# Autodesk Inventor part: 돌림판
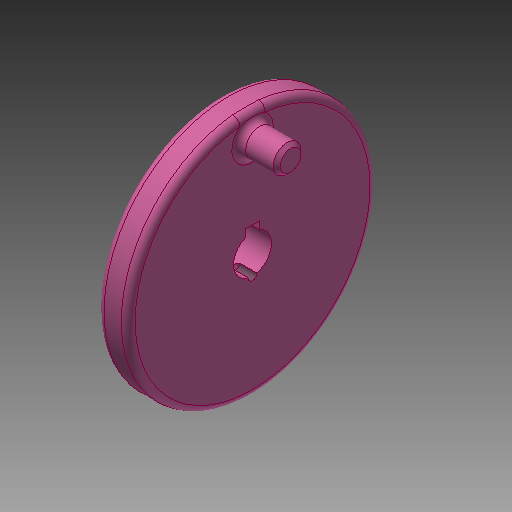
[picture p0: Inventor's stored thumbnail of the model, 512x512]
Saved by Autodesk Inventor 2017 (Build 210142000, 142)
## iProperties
Created: 2019-09
Part Number: 돌림판
Material: 알루미늄 6061
Document SubType Name: Modeling
Designer: mduedu
Density: 2.71 g/cm^3
Mass: 83.7231 g
Surface Area: 107.333 cm^2
Volume: 30.8941 cm^3
Appearance: 분홍색
Author: mduedu
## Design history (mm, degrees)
sketch "스케치1"
  geometry: L1 (0, 0)-(9, 0); L2 (9, 0)-(9, 36); L3 (9, 36)-(0, 36); L4 (0, 23)-(4, 23); L5 (4, 23)-(4, 10); L6 (4, 10)-(0, 10); L7 (0, 36)-(0, 23); L8 (0, 10)-(0, 0)
  constraints: 16 end point, 4 parallel, 2 horizontal, 2 perpendicular, 1 collinear
  dimensions: "d0" = 72 diameter of L3 L1; "d2" = 9 distance of L2.end L3.end; "d3" = 4 distance between parallel lines of L7 L5; "d4" = 20 diameter of L6 L1; "d5" = 46 diameter of L4 L1
revolve "회전1" sketch "스케치1" stored, may be unused: angle "d6" = 90 deg
fillet "모깎기1" dims "d7" = 3
sketch "스케치2"
  geometry: C1 r 4 at (0, 29); 1 further point
  constraints: 1 centre point, 1 vertical alignment
  dimensions: "d8" = 8 diameter of C1; "d9" = 29 distance of C1.centre point (0, 0)
extrude "돌출1" join sketch "스케치2" distance "d10" = 11; taper "d11" = 0 deg
fillet "모깎기2" dims "d12" = 2
fillet "모깎기3" dims "d13" = 2
chamfer "모따기1" distance "d14" = 1; stored, may be unused: second distance "d15" = 2, angle "d16" = 45 deg
sketch "스케치3"
  geometry: L1 (-2, 5.123)-(2, 5.123); L2 (2, 5.123)-(2, 7.3); L3 (2, 7.3)-(-2, 7.3); L4 (-2, 7.3)-(-2, 5.123); A1 r 5.5 centre (0, 0) between (-2, 5.123) and (2, 5.123); 1 further point
  constraints: 8 end point, 2 parallel, 2 point on circle, 1 centre point, 1 coincident, 1 horizontal, 1 perpendicular
  dimensions: "d17" = 11 diameter of A1; "d18" = 4 distance of L2.end L3.end; "d19" = 12.8 dimension on A1 L3
extrude "돌출2" cut sketch "스케치3" stored distance "d20" = 11; taper "d21" = 0 deg
chamfer "모따기2" distance "d22" = 0.5; stored, may be unused: second distance "d23" = 2, angle "d24" = 45 deg
sketch "스케치4"
  geometry: A1 r 5.5 centre (0, 0) between (-2, 5.123) and (2, 5.123) reference; 2 further points
  constraints: 1 point on circle
hole "구멍1" sketch "스케치4" at (0, -5.5) diameter "d25" = 2.459; stored, may be unused: countersink angle "d29" = 90 deg, drill point angle "d31" = 118 deg; dims "d26" = 6, "d27" = 4, "d28" = 2, "d30" = 5
node "솔리드1"
